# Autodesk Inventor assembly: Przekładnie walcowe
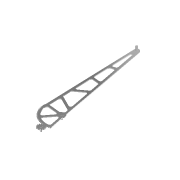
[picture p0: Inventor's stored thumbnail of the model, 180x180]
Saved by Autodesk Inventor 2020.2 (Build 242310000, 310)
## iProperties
Manager: www.cadconsulting.pl
Company: Fabian Stasiak CAD Consulting
ClientObjectVersion: 1
Created: 2014-10
Part Number: Przekładnie walcowe
Document SubType Name: Assembly
Designer: F.Stasiak
Categories: <?xml version="1.0" encoding="UTF-16"?> <MemberInstance><Categories><FamilyTemplate/><ParamToTemplateMap><ParamToTemplate><ParamToTemplate CategoryParameter="//
Catalog Web Link: www.expertbooks.pl
Author: F.Stasiak
Subject: Zbiór ćwiczeń. Autodesk Inventor 2020. Kurs Professional
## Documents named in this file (3)
- C:\2020_Kurs_Professional\R3 Dynamika\300-01-SD\Design Accelerator\Przekładnie walcowe1.iam
- C:\2020_Kurs_Professional\R3 Dynamika\300-01-SD\Design Accelerator\Przekładnia walcowa11.ipt
- C:\2020_Kurs_Professional\R3 Dynamika\300-01-SD\Design Accelerator\Przekładnia walcowa21.ipt
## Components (2 placed, 2 different names)
1. Przekładnia walcowa1:1 — Obrót:1
2. Przekładnia walcowa2:1 — Obrót:1
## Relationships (1: RelateRotation 1)
- Obrót:1 [RelateRotation]: Przekładnia walcowa1:1 ↔ Przekładnia walcowa2:1
